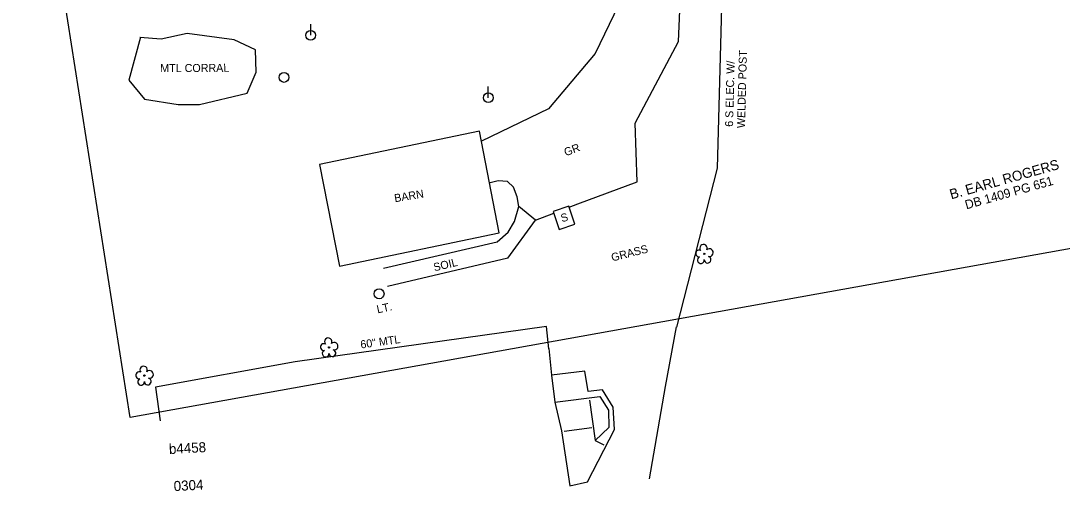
# Model space of a CAD drawing. Extents: x 1316460 to 1321645, y 684173 to 687077.
# Drawn here: x 1318676 to 1319196, y 685018 to 685253 of the extents above; entities that cross this region are included whole.
import ezdxf

# ---------------------------------------------------------------- set-up
doc = ezdxf.new("R2010")
doc.units = 0
for name, color, linetype in [('Exist Building', 7, 'Continuous'), ('Exist Building Text', 7, 'Continuous'), ('Exist Hydrographic Confluence Cogo Description', 7, 'Continuous'), ('Exist Hydrographic Water Surface Cogo Number', 7, 'Continuous'), ('Exist Other Culture Fence Line', 7, 'Continuous'), ('Exist Other Culture Fence Line Text', 7, 'Continuous'), ('Exist Property Deed Book Text', 7, 'Continuous'), ('Exist Property Owner Text', 7, 'Continuous'), ('Exist Roads Soil Text', 7, 'Continuous'), ('Exist Utilities Other Pole CELL', 7, 'Continuous'), ('Exist Utilities Other Pole Text', 7, 'Continuous'), ('Exist Utilities Power Pole CELL', 7, 'Continuous'), ('Exist Vegetation Tree Cogo Elevation', 7, 'Continuous'), ('Exist Vegetation Tree Text', 7, 'Continuous'), ('Old_Level_59', 7, 'Continuous')]:
    doc.layers.add(name, color=color, linetype=linetype)

# ---------------------------------------------------------------- blocks, each defined once
blk = doc.blocks.new('EXIST VEGETATION TREE')
at = {"layer": 'Exist Hydrographic Confluence Cogo Description'}
blk.add_line((0, 0), (0, 0), dxfattribs=at)
blk.add_circle((0, 0), 0.00652, dxfattribs=at)
for centre, radius, start, end in [((-0.052, 0.003), 0.0345, 62.6636, 279.3457), ((-0.008, 0.057), 0.0371, 330.1651, 219.7134), ((0.051, 0.012), 0.038, 257.1011, 134.1999), ((-0.034, -0.062), 0.0338, 111.5671, 6.231), ((0.033, -0.058), 0.034, 181.2822, 74.56)]:
    blk.add_arc(centre, radius, start, end, dxfattribs=at)
blk = doc.blocks.new('EXIST UTILITIES OTHER POLE')
at = {"layer": 'Exist Utilities Other Pole CELL'}
blk.add_circle((0, 0), 0.0493, dxfattribs=at)
blk = doc.blocks.new('EXIST UTILITIES POWER POLE')
at = {"layer": 'Exist Utilities Power Pole CELL'}
for q in [(0, 0.1125), (0, 0)]:
    blk.add_line((0, 0), q, dxfattribs=at)
blk.add_circle((0, 0), 0.049, dxfattribs=at)

msp = doc.modelspace()

# ---------------------------------------------------------------- linework, layer by layer
at = {"layer": 'Exist Building'}
for points in [[(1318904.99, 685197.77), (1318824.85, 685181.14), (1318834.92, 685130.36), (1318914.72, 685146.92)], [(1318949.6, 685160.28), (1318941.8, 685157.69), (1318944.68, 685148.66), (1318952.54, 685151.27)]]:
    msp.add_lwpolyline(points, close=True, dxfattribs=at)
at = {"layer": 'Exist Hydrographic Water Surface Cogo Number'}
msp.add_line((1318919.08, 685134.35), (1318858.89, 685120.13), dxfattribs=at)
for points in [[(1318949.81, 685159.84), (1318954, 685161.44), (1318983.76, 685172.44), (1318982.8, 685201.82), (1319004.37, 685242.54), (1319005.46, 685265.89), (1319000.13, 685282.66), (1318999.57, 685293.66)], [(1318959.83, 685283.41), (1318972.24, 685278.37), (1318974.33, 685260.71), (1318962.7, 685236.65), (1318939.39, 685208.98), (1318905.94, 685192.78)], [(1318856.95, 685129.38), (1318913.74, 685142.42), (1318919.22, 685147.36), (1318922.4, 685152.64), (1318924.61, 685160.08), (1318923.69, 685165.01), (1318921.93, 685169.75), (1318918.83, 685172.66), (1318914.29, 685173), (1318909.58, 685171.82)], [(1318919.08, 685134.35), (1318932.86, 685153.37), (1318942.06, 685156.88)]]:
    msp.add_lwpolyline(points, dxfattribs=at)
at = {"layer": 'Exist Other Culture Fence Line'}
for points in [[(1319026.18, 685272.27), (1319023.76, 685179.36), (1319003.35, 685099.89)], [(1318735.47, 685244.83), (1318729.62, 685223.24), (1318737.36, 685213.8), (1318754.27, 685211.04), (1318764.9, 685211.09), (1318788.72, 685216.71), (1318793.33, 685227.29), (1318792.85, 685238.47), (1318782.3, 685243.49), (1318758.75, 685246.65), (1318745.85, 685243.82), (1318735.02, 685244.63)], [(1318939.61, 685089.08), (1318938.35, 685100.17), (1318812.75, 685082.52), (1318742.92, 685069.87), (1318745.35, 685053.11)], [(1319003.26, 685100), (1318997.65, 685070.22), (1318989.75, 685024.1)], [(1318939.64, 685089.11), (1318940.97, 685075.91), (1318942.5, 685062.36), (1318945.97, 685048.07), (1318950.09, 685020.5)], [(1318950.09, 685020.5), (1318958.83, 685022.48), (1318972.41, 685048.72), (1318971.67, 685059.89), (1318966.48, 685068.59), (1318959.25, 685067.73), (1318957.64, 685077.94), (1318940.97, 685075.91)], [(1318942.5, 685062.36), (1318965.02, 685065.23), (1318969.46, 685058.39), (1318969.61, 685049.68), (1318962.81, 685043.28), (1318967.13, 685041.03)], [(1318959.95, 685063.32), (1318962.81, 685043.28)], [(1318961.03, 685049.48), (1318947.23, 685047.74)]]:
    msp.add_lwpolyline(points, dxfattribs=at)
at = {"layer": 'Exist Vegetation Tree Cogo Elevation'}
msp.add_lwpolyline([(1318932.86, 685153.37), (1318924.61, 685160.08)], dxfattribs=at)
at = {"layer": 'Old_Level_59'}
msp.add_lwpolyline([(1318697.3, 685264.68), (1318675.61, 685496.37), (1319013.72, 685603.72), (1319178.5, 686302.95), (1319290.7, 686462.26), (1319434.76, 686395.34), (1319426.96, 685366.75), (1319230.41, 685144.48), (1318730.33, 685054.78)], close=True, dxfattribs=at)

# ---------------------------------------------------------------- block references
at = {"layer": 'Exist Hydrographic Confluence Cogo Description', "xscale": 50, "yscale": 50}
for p in [(1319017.29, 685136.5), (1318829.72, 685089.75), (1318737.41, 685075.64)]:
    msp.add_blockref('EXIST VEGETATION TREE', p, dxfattribs=at)
at = {"layer": 'Exist Utilities Other Pole CELL', "xscale": 50, "yscale": 50}
for p in [(1318807.2, 685224.66), (1318854.71, 685116.52)]:
    msp.add_blockref('EXIST UTILITIES OTHER POLE', p, dxfattribs=at)
at = {"layer": 'Exist Utilities Power Pole CELL', "xscale": 50, "yscale": 50}
for p in [(1318820.51, 685245.69), (1318909.29, 685214.5)]:
    msp.add_blockref('EXIST UTILITIES POWER POLE', p, dxfattribs=at)

# ---------------------------------------------------------------- texts
at = {"layer": 'Exist Building Text'}
for s, rotation, p in [('BARN', 9.2726, (1318862.63, 685162.26)), ('S', 16.0324, (1318946.16, 685152.26))]:
    msp.add_text(s, height=4, rotation=rotation, dxfattribs=at).set_placement(p)
at = {"layer": 'Exist Other Culture Fence Line Text'}
for s, rotation, p in [(' WELDED POST', 88.5115, (1319037.59, 685197.79)), ('6 S ELEC. W/', 88.5115, (1319031.64, 685199.94)), ('MTL CORRAL', 0.2951, (1318745.34, 685227.28)), ('60" MTL', 8.0009, (1318845.66, 685089.16))]:
    msp.add_text(s, height=4, rotation=rotation, dxfattribs=at).set_placement(p)
at = {"layer": 'Exist Property Deed Book Text'}
msp.add_text('DB 1409 PG 651', height=4.5, rotation=15.7349, dxfattribs=at).set_placement((1319148.32, 685158.71))
at = {"layer": 'Exist Property Owner Text'}
msp.add_text('B. EARL ROGERS', height=5, rotation=15.7349, dxfattribs=at).set_placement((1319140.75, 685163.69))
at = {"layer": 'Exist Roads Soil Text'}
for s, rotation, p in [('GR', 20.8985, (1318948.07, 685185.2)), ('SOIL', 13.2942, (1318882.38, 685127.73))]:
    msp.add_text(s, height=4, rotation=rotation, dxfattribs=at).set_placement(p)
at = {"layer": 'Exist Utilities Other Pole Text'}
msp.add_text('LT.', height=4, rotation=12.0948, dxfattribs=at).set_placement((1318853.98, 685106.74))
at = {"layer": 'Exist Vegetation Tree Text'}
msp.add_text('GRASS', height=4, rotation=14.2501, dxfattribs=at).set_placement((1318971.33, 685132.64))
at = {"layer": 'Old_Level_59'}
for s, p in [('b4458', (1318749.77, 685036.44)), ('0304', (1318752.17, 685017.91))]:
    msp.add_text(s, height=5, rotation=3.1221, dxfattribs=at).set_placement(p)

doc.saveas('drawing.dxf')
